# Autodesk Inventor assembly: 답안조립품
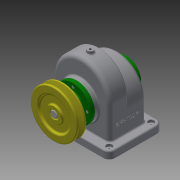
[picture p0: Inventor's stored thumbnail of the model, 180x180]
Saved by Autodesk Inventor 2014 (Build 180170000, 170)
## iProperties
Created: 2017-11
Part Number: 답안조립품
Document SubType Name: Assembly
Designer: net
Author: net
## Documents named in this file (14)
- C:\Users\net\Desktop\471107V1024\답안조립품.iam
- C:\Users\net\Desktop\471107V1024\본체.ipt
- C:\Users\net\Desktop\471107V1024\앞커버.ipt
- C:\Users\net\Desktop\471107V1024\뒤커버.ipt
- C:\Users\net\Desktop\471107V1024\볼트 M3 x 8.ipt
- C:\Users\net\Desktop\471107V1024\오일 실 15 30 7.ipt
- C:\Users\net\Desktop\471107V1024\베어링 6002.ipt
- C:\Users\net\Desktop\471107V1024\축.ipt
- C:\Users\net\Desktop\471107V1024\멈춤나사 - M4 x 10.ipt
- 멈춤나사 - M4 x 10.ipt
- C:\Users\net\Desktop\471107V1024\스퍼기어.ipt
- C:\Users\net\Desktop\471107V1024\키 - 5 x 5 x 18.ipt
- C:\Users\net\Desktop\471107V1024\키 - 6 x 6 x 22.ipt
- C:\Users\net\Desktop\471107V1024\V-벨트풀리.ipt
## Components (1 placed, 1 different names)
1. V-벨트풀리:1 — 각도:1
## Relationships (1: Angle 1)
- 각도:1 [Angle]: V-벨트풀리:1
